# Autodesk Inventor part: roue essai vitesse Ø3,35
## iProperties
Created: 2011-11
Part Number: roue essai vitesse Ø3,35
Document SubType Name: Modeling
Designer: Laur
Density: 1 g/cm^3
Author: Laur
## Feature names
1. Extrusion1
2. Extrusion2
3. Extrusion3
